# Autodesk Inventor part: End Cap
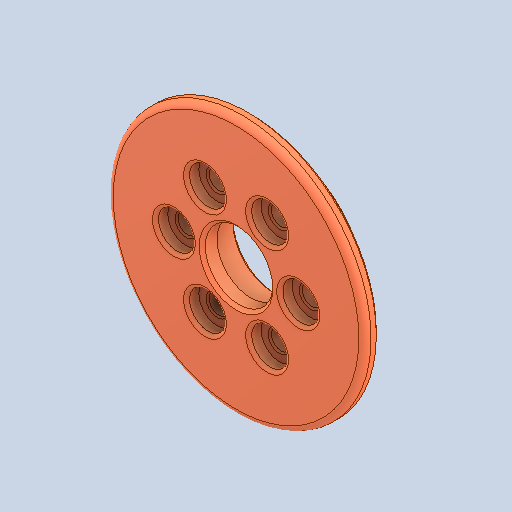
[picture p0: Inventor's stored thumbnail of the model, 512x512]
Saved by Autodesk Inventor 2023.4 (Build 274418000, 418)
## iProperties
Created: 2025-06
Part Number: End Cap
Material: Steel
Document SubType Name: Modeling
Designer: mel
Density: 7.85 g/cm^3
Appearance: Par défaut
Author: mel
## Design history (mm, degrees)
feature "End Cap"
node "Solide1"
